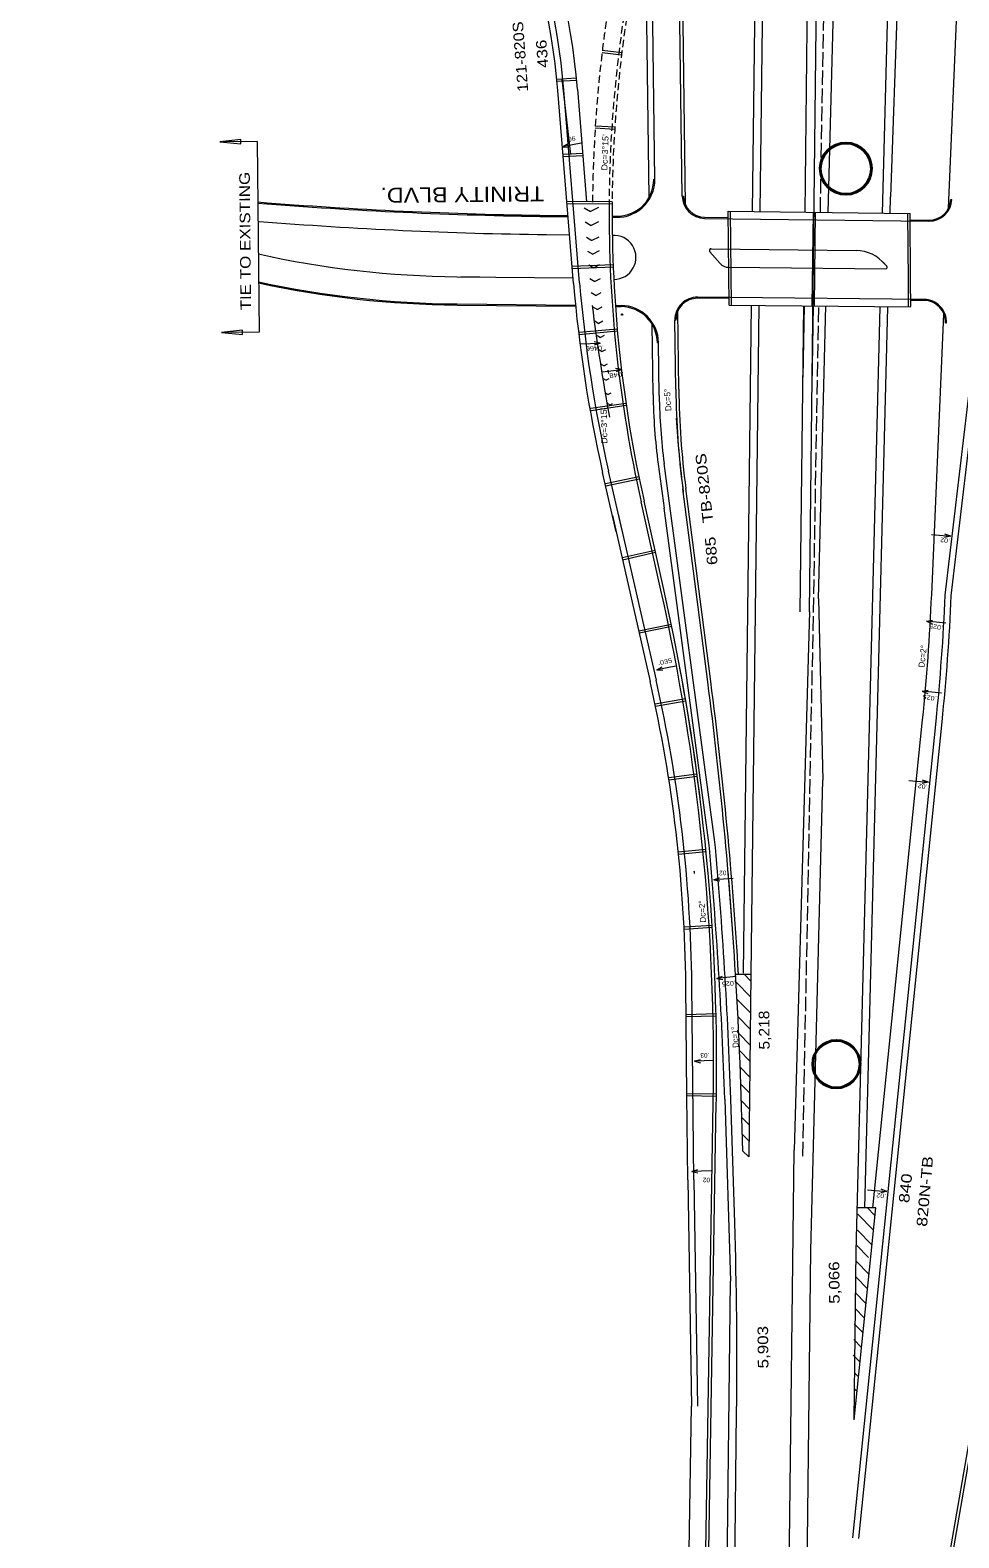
# Model space of a CAD drawing. Extents: x 2354993 to 2372084, y 6966390 to 6990057.
# Drawn here: x 2363436 to 2364667, y 6974745 to 6976742 of the extents above; entities that cross this region are included whole.
import ezdxf

# ---------------------------------------------------------------- set-up
doc = ezdxf.new("R2010")
doc.units = 0
doc.header["$LTSCALE"] = 3.2
doc.header["$PDMODE"] = 32
doc.header["$PDSIZE"] = 1.6
doc.linetypes.add('LONG_DASHED', pattern=[7.5, 6, -1.5])
doc.linetypes.add('MEDIUM_DASHED', pattern=[4.5, 3, -1.5])
for name, color, linetype, lineweight in [('1', 7, 'Continuous', 35), ('12', 7, 'Continuous', 13), ('13', 7, 'Continuous', 13), ('15', 7, 'Continuous', 13), ('17', 7, 'Continuous', 13), ('19', 7, 'Continuous', 13), ('25', 7, 'Continuous', 13), ('4', 7, 'Continuous', 13), ('5', 7, 'Continuous', 13), ('59', 7, 'Continuous', 13), ('61', 7, 'Continuous', 13), ('9', 7, 'Continuous', 13)]:
    doc.layers.add(name, color=color, linetype=linetype, lineweight=lineweight)

msp = doc.modelspace()

# ---------------------------------------------------------------- linework, layer by layer
at = {"layer": '1', "lineweight": 40}
for centre, radius in [((2364517.156, 6976558.555), 33.871), ((2364504.602, 6975372.725), 31.346)]:
    msp.add_circle(centre, radius, dxfattribs=at)
at = {"layer": '12'}
for p, q in [((2364220.257, 6976711.848), (2364194.449, 6976714.999)), ((2364219.897, 6976708.869), (2364194.088, 6976712.022)), ((2364133.973, 6976677.267), (2364159.889, 6976678.781)), ((2364134.463, 6976674.273), (2364160.421, 6976675.79)), ((2364211.052, 6976613.311), (2364185.106, 6976614.994)), ((2364210.86, 6976610.318), (2364184.914, 6976612.001)), ((2364142.53, 6976577.625), (2364168.486, 6976579.108)), ((2364142.702, 6976574.452), (2364168.659, 6976575.935)), ((2364207.447, 6976514.419), (2364147.557, 6976514.903)), ((2364207.426, 6976511.42), (2364147.802, 6976511.901)), ((2364365.503, 6976377.938), (2364364.413, 6976502.287)), ((2364473.677, 6976500.882), (2364472.212, 6976376.913)), ((2364476.676, 6976500.845), (2364475.212, 6976376.884)), ((2364600.009, 6976409.93), (2364599.244, 6976499.34)), ((2364208.761, 6976431.2), (2364154.576, 6976428.959)), ((2364208.882, 6976428.202), (2364154.82, 6976425.966)), ((2364600.298, 6976375.862), (2364600.009, 6976409.929)), ((2364214.213, 6976346.179), (2364163.688, 6976341.61)), ((2364214.481, 6976343.191), (2364163.957, 6976338.622)), ((2364225.766, 6976247.764), (2364179.442, 6976240.906)), ((2364226.203, 6976244.796), (2364179.88, 6976237.938)), ((2364242.847, 6976150.358), (2364198.654, 6976141.231)), ((2364243.451, 6976147.42), (2364199.26, 6976138.293)), ((2364264.361, 6976053.073), (2364220.592, 6976043.251)), ((2364265.018, 6976050.146), (2364221.248, 6976040.323)), ((2364285.945, 6975955.107), (2364242.71, 6975946.195)), ((2364286.552, 6975952.169), (2364243.315, 6975943.257)), ((2364304.638, 6975856.27), (2364264.508, 6975849.448)), ((2364305.14, 6975853.312), (2364265.011, 6975846.49)), ((2364319.874, 6975756.807), (2364282.37, 6975751.77)), ((2364320.273, 6975753.834), (2364282.768, 6975748.797)), ((2364331.63, 6975656.874), (2364295.111, 6975653.262)), ((2364331.924, 6975653.887), (2364295.406, 6975650.275)), ((2364339.896, 6975556.492), (2364302.698, 6975554.122)), ((2364340.087, 6975553.498), (2364302.889, 6975551.127)), ((2364345.101, 6975439.16), (2364305.463, 6975438.251)), ((2364345.169, 6975436.16), (2364305.532, 6975435.251)), ((2364345.646, 6975329.954), (2364306.637, 6975330.608)), ((2364345.687, 6975332.954), (2364306.687, 6975333.608))]:
    msp.add_line(p, q, dxfattribs=at)
for radius, start in [(48.5, 262.08834), (50, 262.33221)]:
    msp.add_arc((2364214.072, 6976544.083), radius, start, 0.75286, dxfattribs=at)
at = {"layer": '15'}
for p, q in [((2363737.301, 6976594.496), (2363687.464, 6976594.035)), ((2363737.301, 6976594.496), (2363739.638, 6976342.006)), ((2363739.638, 6976342.006), (2363689.801, 6976341.545))]:
    msp.add_line(p, q, dxfattribs=at)
for points in [[(2363687.464, 6976594.035), (2363715.49, 6976591.295), (2363715.435, 6976597.294)], [(2363689.801, 6976341.545), (2363717.827, 6976338.805), (2363717.772, 6976344.804)]]:
    msp.add_lwpolyline(points, close=True, dxfattribs=at)
at = {"layer": '17'}
for p, q in [((2364141.227, 6976587.593), (2364148.646, 6976591.34)), ((2364191.5, 6976327.281), (2364183.578, 6976324.764))]:
    msp.add_line(p, q, dxfattribs=at)
for points in [[(2364166.545, 6976592.466), (2364141.227, 6976587.593), (2364149.501, 6976586.869)], [(2364165.729, 6976326.505), (2364191.5, 6976327.281), (2364183.447, 6976329.314)]]:
    msp.add_lwpolyline(points, dxfattribs=at)
at = {"layer": '19'}
for p, q in [((2364201.86, 6976291.634), (2364202.424, 6976287.331)), ((2364220.228, 6976292.798), (2364212.603, 6976289.49)), ((2364656.189, 6976071.819), (2364648.034, 6976070.216)), ((2364623.803, 6975959.304), (2364631.519, 6975956.212)), ((2364266.473, 6975895.028), (2364273.894, 6975898.772)), ((2364618.261, 6975866.445), (2364625.977, 6975863.353)), ((2364626.461, 6975746.048), (2364618.306, 6975744.445)), ((2364342.025, 6975617.021), (2364349.845, 6975619.84)), ((2364346.086, 6975486.183), (2364353.826, 6975489.214)), ((2364316.438, 6975376.461), (2364324.327, 6975379.082)), ((2364313.124, 6975230.56), (2364321.013, 6975233.181)), ((2364571.644, 6975204.112), (2364563.489, 6975202.509))]:
    msp.add_line(p, q, dxfattribs=at)
for points in [[(2364194.67, 6976289.408), (2364220.228, 6976292.798), (2364212.01, 6976294.003)], [(2364630.496, 6976073.972), (2364656.189, 6976071.819), (2364648.419, 6976074.753)], [(2364649.449, 6975956.645), (2364623.803, 6975959.304), (2364631.982, 6975960.742)], [(2364291.794, 6975899.89), (2364266.473, 6975895.028), (2364274.748, 6975894.299)], [(2364643.907, 6975863.786), (2364618.261, 6975866.445), (2364626.44, 6975867.883)], [(2364600.768, 6975748.201), (2364626.461, 6975746.048), (2364618.691, 6975748.982)], [(2364367.749, 6975618.785), (2364342.025, 6975617.021), (2364350.151, 6975615.297)], [(2364371.752, 6975488.648), (2364346.086, 6975486.183), (2364354.256, 6975484.681)], [(2364342.199, 6975377.575), (2364316.438, 6975376.461), (2364324.518, 6975374.532)], [(2364338.885, 6975231.674), (2364313.124, 6975230.56), (2364321.204, 6975228.631)], [(2364545.951, 6975206.265), (2364571.644, 6975204.112), (2364563.874, 6975207.046)]]:
    msp.add_lwpolyline(points, dxfattribs=at)
at = {"layer": '25'}
for p, q in [((2364530.922, 6975124.614), (2364562.664, 6976375.097)), ((2364291.753, 6976266.396), (2364290.548, 6976357.962)), ((2364334.203, 6975878.802), (2364301.128, 6976134.434)), ((2364470.941, 6975126.137), (2364486.746, 6975748.807)), ((2364556.956, 6975182.505), (2364533.106, 6975182.46))]:
    msp.add_line(p, q, dxfattribs=at)
for centre, radius, start, end in [((2364320.545, 6976358.356), 30, 89.45039, 180.7541), ((2364320.545, 6976358.356), 28.5, 89.45039, 180.7541), ((2365437.57, 6976281.475), 1145.916, 180.75397, 187.37241), ((2358651.991, 6975143.593), 5729.578, 3.48146, 7.37242)]:
    msp.add_arc(centre, radius, start, end, dxfattribs=at)
at = {"layer": '4'}
for centre, radius, start, end in [((2367023.768, 6976739.288), 2865.742, 187.25475, 190.24927), ((2365933.209, 6976336.345), 1644.505, 183.76571, 187.20199), ((2359028.554, 6975149.626), 5309.334, 5.14125, 5.17258), ((2358640.15, 6975142.702), 5741.452, 3.90795, 4.84638)]:
    msp.add_arc(centre, radius, start, end, dxfattribs=at)
at = {"layer": '5', "linetype": 'LONG_DASHED'}
for p, q in [((2364483.383, 6976501.515), (2364499.337, 6977426.187)), ((2364474.238, 6975971.435), (2364481.232, 6976376.826)), ((2364460.157, 6975250.802), (2364474.238, 6975971.435))]:
    msp.add_line(p, q, dxfattribs=at)
at = {"layer": '5'}
for p, q in [((2364463.051, 6976501.012), (2364473.085, 6977351.601)), ((2364468.806, 6975971.515), (2364485.084, 6977351.459)), ((2364401.898, 6977227.474), (2364393.18, 6976501.87)), ((2364410.695, 6977127.236), (2364403.178, 6976501.747)), ((2364264.089, 6976544.74), (2364257.91, 6977015.279)), ((2364256.409, 6976520.423), (2364250.238, 6976989.323)), ((2364493.827, 6976500.634), (2364506.22, 6976988.835)), ((2364592.679, 6976978.427), (2364576.375, 6976521.182)), ((2364300.388, 6976522.254), (2364296.153, 6976843.963)), ((2364304.541, 6976510.635), (2364300.153, 6976844.016)), ((2364565.808, 6976498.964), (2364574.043, 6976823.383)), ((2364653.122, 6976506.192), (2364666.284, 6976808.9)), ((2364156.395, 6976406.689), (2364135.555, 6976661.848)), ((2364164.368, 6976407.34), (2364143.529, 6976662.499)), ((2364161.469, 6976663.965), (2364173.652, 6976514.8)), ((2364262.568, 6976544.72), (2364264.067, 6976544.74)), ((2364300.388, 6976522.254), (2364301.888, 6976522.273)), ((2364575.805, 6976498.71), (2364576.378, 6976521.284)), ((2364656.126, 6976517.745), (2364657.625, 6976517.68)), ((2364123.617, 6976495.195), (2364149.192, 6976494.879)), ((2364123.635, 6976496.695), (2364149.069, 6976496.381)), ((2364170.291, 6976506.807), (2364178.765, 6976501.813)), ((2364189.404, 6976507.068), (2364178.765, 6976501.813)), ((2364330.033, 6976494.151), (2364361.488, 6976493.763)), ((2364362.502, 6976377.967), (2364361.414, 6976502.26)), ((2364361.414, 6976502.26), (2364602.244, 6976499.303)), ((2364370.176, 6976502.124), (2364370.176, 6976502.154)), ((2364603.008, 6976409.955), (2364602.244, 6976499.303)), ((2364171.823, 6976488.054), (2364179.575, 6976483.485)), ((2364189.432, 6976488.353), (2364179.575, 6976483.485)), ((2364330.015, 6976492.651), (2364627.284, 6976488.986)), ((2364602.317, 6976490.794), (2364627.302, 6976490.486)), ((2364120.669, 6976471.23), (2364151.154, 6976470.854)), ((2364173.477, 6976467.794), (2364180.633, 6976463.577)), ((2364189.687, 6976468.048), (2364180.633, 6976463.577)), ((2364174.971, 6976449.502), (2364181.753, 6976445.505)), ((2364190.12, 6976449.638), (2364181.753, 6976445.505)), ((2364336.964, 6976448.401), (2364350.554, 6976433.023)), ((2364338.869, 6976452.556), (2364530.747, 6976450.191)), ((2364566.457, 6976434.552), (2364571.393, 6976429.333)), ((2364002.302, 6976415.429), (2364155.802, 6976413.952)), ((2364006.399, 6976415.384), (2364032.152, 6976415.14)), ((2364176.465, 6976431.212), (2364183.032, 6976427.341)), ((2364190.748, 6976431.153), (2364183.032, 6976427.341)), ((2364361.651, 6976427.956), (2364569.921, 6976425.959)), ((2364177.959, 6976412.919), (2364184.474, 6976409.079)), ((2364179.511, 6976394.592), (2364186.08, 6976390.719)), ((2364191.576, 6976412.587), (2364184.474, 6976409.079)), ((2364192.604, 6976393.942), (2364186.08, 6976390.719)), ((2364603.297, 6976375.834), (2364603.008, 6976409.954)), ((2364001.941, 6976377.929), (2364159.127, 6976376.416)), ((2364001.955, 6976379.429), (2364158.979, 6976377.918)), ((2364181.117, 6976376.233), (2364187.856, 6976372.262)), ((2364193.836, 6976375.216), (2364187.856, 6976372.262)), ((2364211.726, 6976377.411), (2364219.404, 6976377.336)), ((2364211.832, 6976375.91), (2364219.389, 6976375.836)), ((2364362.428, 6976386.456), (2364320.819, 6976386.855)), ((2364620.831, 6976385.478), (2364320.833, 6976388.355)), ((2364362.722, 6976377.965), (2364603.299, 6976375.652)), ((2364391.688, 6976377.687), (2364381.059, 6975493.135)), ((2364401.688, 6976377.59), (2364391.039, 6975491.379)), ((2364456.807, 6975971.657), (2364461.589, 6976377.014)), ((2364480.837, 6975988.89), (2364490.682, 6976376.735)), ((2364542.394, 6975182.478), (2364572.661, 6976374.843)), ((2364620.817, 6976383.978), (2364603.227, 6976384.147)), ((2364183.59, 6976357.364), (2364189.801, 6976353.703)), ((2364195.276, 6976356.408), (2364189.801, 6976353.703)), ((2364292.048, 6976357.981), (2364290.548, 6976357.962)), ((2364295.753, 6976266.449), (2364294.394, 6976369.687)), ((2364630.871, 6975994.486), (2364647.026, 6976366.008)), ((2364649.017, 6976354.241), (2364650.515, 6976354.176)), ((2364186.203, 6976338.413), (2364191.923, 6976335.042)), ((2364196.925, 6976337.513), (2364191.923, 6976335.042)), ((2364261.819, 6976259.529), (2364260.601, 6976352.14)), ((2364188.957, 6976319.377), (2364194.221, 6976316.274)), ((2364198.79, 6976318.531), (2364194.221, 6976316.274)), ((2364267.418, 6976327.975), (2364268.918, 6976327.994)), ((2364269.836, 6976258.002), (2364268.918, 6976327.994)), ((2364191.856, 6976300.257), (2364196.702, 6976297.4)), ((2364200.872, 6976299.46), (2364196.702, 6976297.4)), ((2364648.854, 6975993.703), (2364685.177, 6976299.01)), ((2364656.798, 6975992.758), (2364693.121, 6976298.065)), ((2364194.9, 6976281.051), (2364199.368, 6976278.417)), ((2364203.176, 6976280.298), (2364199.368, 6976278.417)), ((2364198.093, 6976261.757), (2364202.224, 6976259.323)), ((2364205.706, 6976261.043), (2364202.224, 6976259.323)), ((2364200.335, 6976248.675), (2364204.407, 6976245.459)), ((2364207.677, 6976247.074), (2364204.407, 6976245.459)), ((2364212.811, 6976077.429), (2364194.881, 6976156.299)), ((2364220.612, 6976079.202), (2364202.682, 6976158.073)), ((2364268.508, 6976167.044), (2364276.309, 6976108.919)), ((2364343.25, 6975670.276), (2364276.437, 6976168.108)), ((2364338.17, 6975879.315), (2364305.095, 6976134.947)), ((2364272.091, 6976000.348), (2364245.819, 6976117.442)), ((2364275.994, 6976001.224), (2364249.722, 6976118.318)), ((2364207.86, 6976099.217), (2364257.87, 6975879.23)), ((2364215.66, 6976100.99), (2364265.672, 6975880.999)), ((2364335.322, 6975669.213), (2364276.309, 6976108.919)), ((2364588.065, 6974339.557), (2364894.105, 6976105.613)), ((2364592.006, 6974338.873), (2364898.046, 6976104.929)), ((2364480.837, 6975988.89), (2364486.746, 6975748.807)), ((2364468.806, 6975971.515), (2364448.514, 6975258.741)), ((2364526.462, 6974745.451), (2364636.721, 6975826.723)), ((2364534.421, 6974744.639), (2364644.68, 6975825.911)), ((2364552.936, 6975182.498), (2364618.814, 6975828.55)), ((2364306.637, 6975330.608), (2364305.083, 6975477.703)), ((2364315.808, 6975219.612), (2364313.082, 6975477.787)), ((2364391.039, 6975491.379), (2364370.876, 6975491.58)), ((2364390.905, 6975461.658), (2364371.604, 6975481.353)), ((2364391.155, 6975482.834), (2364382.699, 6975491.462)), ((2364390.655, 6975440.483), (2364372.902, 6975458.597)), ((2364390.455, 6975419.26), (2364374.105, 6975435.939)), ((2364390.243, 6975398.048), (2364375.212, 6975413.381)), ((2364390.031, 6975376.836), (2364376.227, 6975390.918)), ((2364389.655, 6975355.791), (2364377.15, 6975368.549)), ((2364389.406, 6975334.618), (2364377.982, 6975346.272)), ((2364307.81, 6975219.527), (2364306.637, 6975330.608)), ((2364320, 6974037.948), (2364341.522, 6975321.854)), ((2364324, 6974037.881), (2364345.522, 6975321.787)), ((2364356.648, 6975326.194), (2364364.464, 6975085.406)), ((2364369.882, 6975162.803), (2364364.645, 6975326.411)), ((2364389.156, 6975313.445), (2364378.725, 6975324.087)), ((2364388.906, 6975292.27), (2364379.435, 6975301.932)), ((2364388.656, 6975271.098), (2364380.144, 6975279.781)), ((2364405.885, 6971647.215), (2364448.514, 6975258.72)), ((2364307.81, 6975219.479), (2364312.78, 6974919.515)), ((2364315.808, 6975219.612), (2364320.778, 6974919.647)), ((2364528.304, 6974901.522), (2364556.956, 6975182.505)), ((2364555.717, 6975172.27), (2364545.376, 6975182.836)), ((2364553.737, 6975152.851), (2364533.009, 6975174.027)), ((2364551.757, 6975133.431), (2364532.789, 6975152.809)), ((2364429.884, 6971646.932), (2364470.958, 6975126.824)), ((2364528.304, 6974901.519), (2364530.952, 6975125.889)), ((2364547.225, 6975116.618), (2364531.522, 6975132.66)), ((2364547.796, 6975094.591), (2364530.861, 6975111.891)), ((2364355.095, 6974291.679), (2364364.464, 6975085.406)), ((2364545.816, 6975075.173), (2364530.2, 6975091.124)), ((2364543.836, 6975055.752), (2364529.539, 6975070.356)), ((2364541.856, 6975036.332), (2364528.879, 6975049.589)), ((2364539.875, 6975016.91), (2364528.218, 6975028.821)), ((2364537.895, 6974997.492), (2364527.557, 6975008.053)), ((2364535.915, 6974978.072), (2364526.896, 6974987.286)), ((2364533.935, 6974958.652), (2364529.037, 6974963.653)), ((2364532.131, 6974939.049), (2364528.787, 6974942.466)), ((2364298.003, 6974038.317), (2364312.777, 6974919.68)), ((2364530.151, 6974919.631), (2364528.537, 6974921.279)), ((2364365.094, 6974291.579), (2364372.415, 6974911.86))]:
    msp.add_line(p, q, dxfattribs=at)
msp.add_lwpolyline([(2364391.039, 6975491.379), (2364388.406, 6975249.925), (2364380.853, 6975257.63)], dxfattribs=at)
for centre, radius, start, end in [((2363030.028, 6976428.641), 1917.859, 350.16881, 38.12295), ((2363030.028, 6976428.641), 1891.859, 350.16881, 38.12295), ((2363030.028, 6976428.641), 1895.859, 350.16881, 38.12295), ((2363278.934, 6976591.886), 885.473, 4.66908, 79.45368), ((2363278.934, 6976591.886), 859.473, 4.66908, 79.45368), ((2363278.934, 6976591.886), 867.473, 4.66908, 79.45368), ((2364194.239, 6982224.338), 5728.078, 265.43333, 269.2949), ((2365952.338, 6976500.332), 1748.947, 179.53746, 192.64601), ((2365952.338, 6976500.332), 1744.947, 179.53746, 192.64601), ((2364330.385, 6976522.648), 30, 180.75408, 269.29367), ((2364330.385, 6976522.648), 28.5, 180.75408, 269.29367), ((2364627.653, 6976518.983), 30, 269.29355, 357.51013), ((2364627.653, 6976518.983), 28.5, 269.29355, 357.51013), ((2364194.239, 6982224.338), 5729.578, 265.43333, 269.2949), ((2364194.239, 6982224.338), 5753.578, 265.46771, 269.26735), ((2364209.911, 6976441.128), 29.142, 269.44369, 94.4484), ((2364014.558, 6977688.61), 1273.24, 257.48616, 269.44843), ((2364338.837, 6976450.057), 2.5, 89.29242, 221.46875), ((2364530.131, 6976400.195), 50, 38.72208, 89.2941), ((2364361.794, 6976442.955), 15, 221.4662, 269.45025), ((2364569.94, 6976427.959), 2, 269.45043, 43.40301), ((2364014.558, 6977688.61), 1310.74, 257.85089, 269.44843), ((2364014.558, 6977688.61), 1309.24, 257.85089, 269.44843), ((2365935.418, 6976551.985), 1784.947, 184.66908, 192.80768), ((2365935.418, 6976551.985), 1776.947, 184.66908, 192.80768), ((2364218.922, 6976327.338), 48.5, 0.75204, 89.44837), ((2364218.922, 6976327.338), 50, 0.75204, 89.44837), ((2364620.544, 6976355.479), 28.5, 357.51013, 89.45048), ((2364620.544, 6976355.479), 30, 357.51013, 89.45048), ((2365019.772, 6976267.872), 758, 180.63068, 187.64408), ((2365019.772, 6976267.872), 750, 180.75406, 187.64408), ((2365437.57, 6976281.475), 1141.916, 180.75397, 187.37241), ((2361463.137, 6975370.103), 2878.789, 359.03966, 12.64601), ((2361463.137, 6975370.103), 2882.789, 359.202, 12.64601), ((2361772.783, 6976118.765), 2860.789, 354.17756, 357.51015), ((2361772.783, 6976118.765), 2878.789, 354.17756, 357.51015), ((2361772.783, 6976118.765), 2886.789, 354.17756, 357.51015), ((2361463.137, 6975370.103), 2882.789, 7.0723, 10.53623), ((2362403.348, 6975457.635), 1901.84, 0.60459, 12.80743), ((2362403.348, 6975457.635), 1909.84, 0.60459, 12.80745), ((2358651.991, 6975143.593), 5733.578, 3.48146, 7.37242), ((2358651.99, 6975143.593), 5707.578, 1.83339, 5.28724), ((2358651.99, 6975143.593), 5715.578, 1.83339, 5.28724), ((2358651.99, 6975143.593), 5729.578, 1.14036, 3.482), ((2361463.137, 6975370.103), 2882.789, 359.03966, 359.202), ((2358642.814, 6974979.492), 5730, 359.32371, 1.83328)]:
    msp.add_arc(centre, radius, start, end, dxfattribs=at)
at = {"layer": '5', "linetype": 'MEDIUM_DASHED'}
for centre, radius, start, end in [((2365952.337, 6976500.333), 1770.947, 142.90202, 179.54796), ((2365952.338, 6976500.332), 1748.947, 143.1115, 179.53746), ((2365952.338, 6976500.332), 1744.947, 143.1512, 179.53746)]:
    msp.add_arc(centre, radius, start, end, dxfattribs=at)
at = {"layer": '59'}
for p, q in [((2364460.597, 6976282.477), (2364462.225, 6976377.008)), ((2364472.412, 6976271.594), (2364474.225, 6976376.942))]:
    msp.add_line(p, q, dxfattribs=at)
at = {"layer": '61'}
msp.add_line((2364140.834, 6976676.787), (2364152.3, 6976577.301), dxfattribs=at)
at = {"layer": '9'}
msp.add_point((2364220.647, 6976365.312), dxfattribs=at)

# ---------------------------------------------------------------- texts
at = {"layer": '12'}
for s, rotation, width, p in [("Dc=3°15'", 87.985, 1.1, (2364201.105, 6976556.063)), ('Dc=1°', 93.639, 0.95, (2364375.156, 6975394.606))]:
    msp.add_text(s, height=8, rotation=rotation, dxfattribs=dict(at, width=width)).set_placement(p)
for s, p in [('Dc=5°', (2364286.07, 6976237.775)), ('Dc=2°', (2364331.92, 6975560.343))]:
    msp.add_text(s, height=8, rotation=93.639, dxfattribs=at).set_placement(p)
at = {"layer": '13'}
for s, rotation, width, p in [('121-820S', 94.338, 1.15, (2364096.276, 6976660.824)), ('436', 94.471, 1.2, (2364123.117, 6976692.438)), ('TB-820S', 96.202, 1.25, (2364341.535, 6976090.401)), ('685', 94.755, 1.2, (2364347.239, 6976034.247)), ('5,218', 90.548, 1.1, (2364416.129, 6975392.092)), ('820N-TB', 84.917, 1.25, (2364624.577, 6975156.965)), ('840', 83.832, 1.25, (2364600.951, 6975188.289)), ('5,066', 90.548, 1.2, (2364508.953, 6975055.436)), ('5,903', 90.548, 1.2, (2364414.579, 6974969.874))]:
    msp.add_text(s, height=14, rotation=rotation, dxfattribs=dict(at, width=width)).set_placement(p)
at = {"layer": '15'}
for s, height, rotation, width, p in [('TIE TO EXISTING', 14, 90.548, 1.2, (2363729.049, 6976370.944)), ('TRINITY BLVD.', 20, 180.548, 1.15, (2364117.385, 6976535.223))]:
    msp.add_text(s, height=height, rotation=rotation, dxfattribs=dict(at, width=width)).set_placement(p)
at = {"layer": '17'}
for s, height, rotation, width, p in [('.06', 6, 10.964, 1.15, (2364146.786, 6976593.577)), ('.0466', 6, 182.937, 1.2, (2364196.621, 6976324.233)), ("Dc=3°15'", 8, 91.084, 1.1, (2364201.219, 6976194.333))]:
    msp.add_text(s, height=height, rotation=rotation, dxfattribs=dict(at, width=width)).set_placement(p)
msp.add_text('Dc=2°', height=8, rotation=83.132, dxfattribs=at).set_placement((2364621.114, 6975897.556))
at = {"layer": '19'}
for s, height, rotation, width, p in [('.048', 6, 187.791, 1.25, (2364222.813, 6976289.649)), ('.02', 6, 171.703, 1.15, (2364655.413, 6976068.334)), ('.025', 6, 171.703, 1.2, (2364646.432, 6975953.335)), ('.035', 5.999, 10.665, 1.25, (2364268.516, 6975900.932)), ('.025', 6, 171.703, 1.2, (2364637.855, 6975859.523)), ('.02', 6, 171.703, 1.15, (2364625.685, 6975742.563)), ('.02', 6, 182.2, 1.1, (2364361.204, 6975629.132)), ('.025', 5.999, 184.969, 1.2, (2364371.173, 6975483.215)), ('.03', 6, 181.281, 1.05, (2364336.153, 6975387.526)), ('.02', 6, 179.223, 1.05, (2364339.456, 6975222.239)), ('.02', 6, 171.703, 1.15, (2364570.868, 6975200.627))]:
    msp.add_text(s, height=height, rotation=rotation, dxfattribs=dict(at, width=width)).set_placement(p)

doc.saveas('drawing.dxf')
